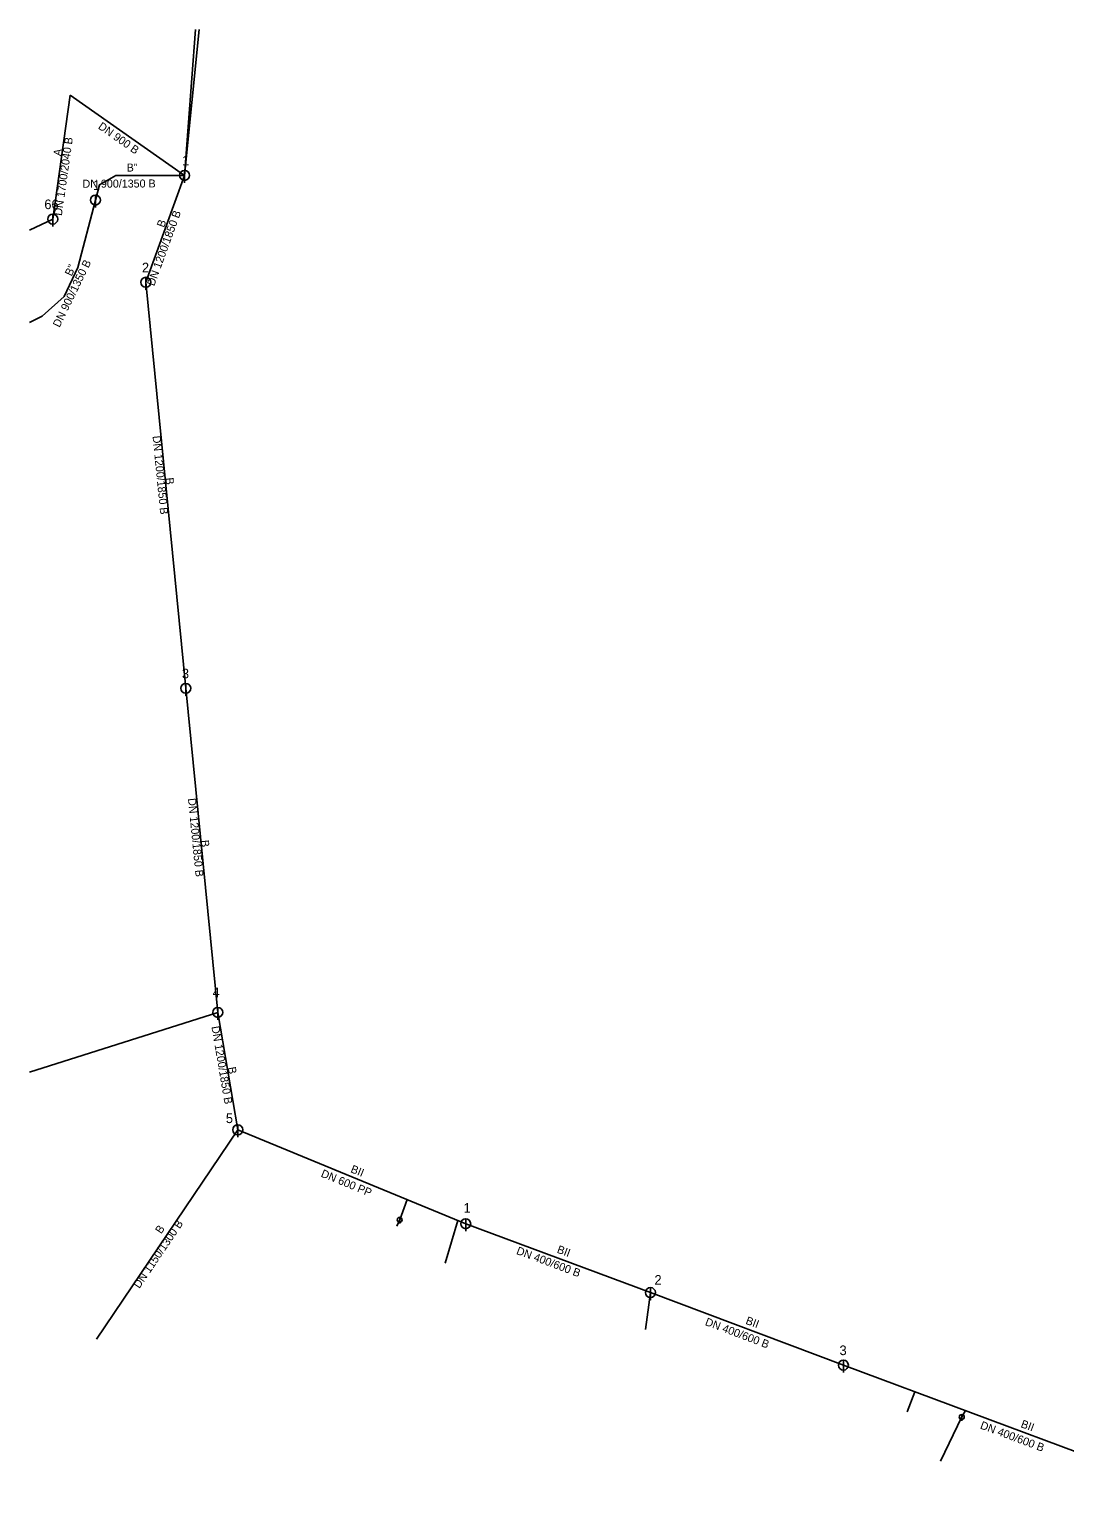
# Model space of a CAD drawing. Extents: x -464617 to -464210, y -1094294 to -1093929.
# Drawn here: x -464616.5 to -464408.8, y -1094224.7 to -1093929.4 of the extents above; entities that cross this region are included whole.
import ezdxf

# ---------------------------------------------------------------- set-up
doc = ezdxf.new("R2010")
doc.units = 0
for name, color, linetype in [('_pripojka_kanal_jednotna_priblizne_', 7, 'Continuous'), ('_stoka_jednotna_smvak_prevzato_z_dokumentace_', 7, 'Continuous'), ('Default', 7, 'Continuous'), ('MoLevel 119', 7, 'Continuous'), ('MoLevel 120', 7, 'Continuous'), ('MoLevel 57', 7, 'Continuous'), ('MoLevel 68', 7, 'Continuous'), ('MoLevel 69', 7, 'Continuous')]:
    doc.layers.add(name, color=color, linetype=linetype)

# ---------------------------------------------------------------- blocks, each defined once
blk = doc.blocks.new('_sachta_kanal_prip_')
at = {"layer": 'Default'}
blk.add_line((0, 0.00005), (0, -0.000075), dxfattribs=at)
blk.add_circle((0, 0), 0.00005, dxfattribs=at)
blk = doc.blocks.new('_sachta_kanal_prevzato_z_dokumentace_')
at = {"layer": 'Default'}
blk.add_line((0, 0.00005), (0, -0.000075), dxfattribs=at)
blk.add_circle((0, 0), 0.00005, dxfattribs=at)

msp = doc.modelspace()

# ---------------------------------------------------------------- linework, layer by layer
at = {"layer": '_pripojka_kanal_jednotna_priblizne_'}
for p, q in [((-464542.23, -1094168.14), (-464540.71, -1094164.09)), ((-464542.83, -1094169.43), (-464542.23, -1094168.14)), ((-464533.08, -1094176.81), (-464530.58, -1094168.26)), ((-464492.92, -1094190.11), (-464491.91, -1094182.73)), ((-464440.4, -1094206.68), (-464438.87, -1094202.63)), ((-464433.73, -1094216.58), (-464429.46, -1094207.69)), ((-464429.46, -1094207.69), (-464428.73, -1094206.41))]:
    msp.add_line(p, q, dxfattribs=at)
at = {"layer": '_stoka_jednotna_smvak_prevzato_z_dokumentace_'}
for p, q in [((-464585.39, -1093958.67), (-464582.43, -1093929.4)), ((-464585.39, -1093958.67), (-464583.21, -1093929.4)), ((-464611.83, -1093967.44), (-464608.31, -1093942.61)), ((-464585.39, -1093958.67), (-464608.31, -1093942.61)), ((-464593.16, -1093980.12), (-464585.39, -1093958.67)), ((-464616.51, -1093969.66), (-464611.83, -1093967.44)), ((-464585.14, -1094061.55), (-464593.16, -1093980.12)), ((-464578.73, -1094126.54), (-464585.14, -1094061.55)), ((-464616.51, -1094138.52), (-464578.73, -1094126.54)), ((-464574.71, -1094150.1), (-464578.73, -1094126.54)), ((-464603.05, -1094192.07), (-464574.71, -1094150.1)), ((-464528.98, -1094168.92), (-464574.71, -1094150.1)), ((-464491.91, -1094182.73), (-464528.98, -1094168.92)), ((-464453.2, -1094197.28), (-464491.91, -1094182.73)), ((-464379.88, -1094224.65), (-464453.2, -1094197.28))]:
    msp.add_line(p, q, dxfattribs=at)
for points in [[(-464603.27, -1093963.62), (-464602.43, -1093960.54), (-464599.17, -1093958.72), (-464585.39, -1093958.67)], [(-464616.51, -1093988.17), (-464613.94, -1093986.89), (-464609.57, -1093982.94), (-464606.78, -1093977.17), (-464603.27, -1093963.62)]]:
    msp.add_lwpolyline(points, dxfattribs=at)

# ---------------------------------------------------------------- block references
at = {"layer": 'MoLevel 119', "xscale": 20000, "yscale": 20000}
for p in [(-464585.39, -1093958.67), (-464603.27, -1093963.62), (-464611.83, -1093967.44), (-464593.16, -1093980.12), (-464585.14, -1094061.55), (-464578.73, -1094126.54), (-464574.71, -1094150.1), (-464528.98, -1094168.92), (-464491.91, -1094182.73), (-464453.2, -1094197.28)]:
    msp.add_blockref('_sachta_kanal_prevzato_z_dokumentace_', p, dxfattribs=at)
at = {"layer": 'MoLevel 57', "xscale": 10000, "yscale": 10000}
for p in [(-464542.23, -1094168.14), (-464429.46, -1094207.69)]:
    msp.add_blockref('_sachta_kanal_prip_', p, dxfattribs=at)

# ---------------------------------------------------------------- texts
at = {"layer": 'MoLevel 120'}
for s, height, p in [('1', 1.93, (-464585.9, -1093956.67)), ('1', 1.93, (-464603.77, -1093961.62)), ('66', 1.926, (-464613.52, -1093965.44)), ('2', 1.93, (-464593.94, -1093978.12)), ('3', 1.93, (-464585.92, -1094059.55)), ('4', 1.93, (-464579.77, -1094123.51)), ('5', 1.93, (-464577.1, -1094148.74)), ('1', 1.93, (-464529.41, -1094166.71)), ('2', 1.93, (-464491.11, -1094181.16)), ('3', 1.93, (-464453.98, -1094195.28))]:
    msp.add_text(s, height=height, dxfattribs=at).set_placement(p)
at = {"layer": 'MoLevel 68'}
for s, height, rotation, p in [('DN 900 B', 1.605, 324.9825, (-464602.87, -1093949.18)), ('DN 1700/2040 B', 1.6049, 81.9371, (-464610.01, -1093966.84)), ('DN 900/1350 B', 1.6049, 0.2121, (-464605.86, -1093961.15)), ('DN 1200/1850 B', 1.6049, 70.1132, (-464591.47, -1093980.98)), ('DN 900/1350 B', 1.6049, 64.1704, (-464610.47, -1093989.29)), ('DN 1200/1850 B', 1.6049, 275.6211, (-464591.81, -1094010.96)), ('DN 1200/1850 B', 1.6049, 275.6346, (-464584.71, -1094083.65)), ('DN 1200/1850 B', 1.6049, 279.683, (-464580, -1094129.42)), ('DN 600 PP', 1.605, 337.6306, (-464558.16, -1094159.45)), ('DN 1150/1300 B', 1.6049, 55.971, (-464594.46, -1094182.03)), ('DN 400/600 B', 1.6049, 339.5677, (-464518.95, -1094174.97)), ('DN 400/600 B', 1.6049, 339.4002, (-464481.09, -1094189.23)), ('DN 400/600 B', 1.6049, 339.5296, (-464425.89, -1094209.97))]:
    msp.add_text(s, height=height, rotation=rotation, dxfattribs=at).set_placement(p)
at = {"layer": 'MoLevel 69'}
for s, height, rotation, p in [('A', 1.6, 81.9371, (-464610.16, -1093954.87)), ('B"', 1.605, 0.2121, (-464597, -1093957.91)), ('B', 1.6, 70.1132, (-464589.51, -1093969.24)), ('B"', 1.605, 64.1704, (-464608.06, -1093979.01)), ('B', 1.6, 275.6211, (-464589.22, -1094019.35)), ('B', 1.6, 275.6346, (-464582.11, -1094092.04)), ('B', 1.6, 279.683, (-464576.71, -1094137.6)), ('BII', 1.605, 337.6306, (-464552.21, -1094158.56)), ('B', 1.6, 55.971, (-464590.08, -1094171.08)), ('BII', 1.605, 339.5677, (-464510.8, -1094174.7)), ('BII', 1.605, 339.4002, (-464472.95, -1094188.98)), ('BII', 1.605, 339.5296, (-464417.74, -1094209.7))]:
    msp.add_text(s, height=height, rotation=rotation, dxfattribs=at).set_placement(p)

doc.saveas('drawing.dxf')
